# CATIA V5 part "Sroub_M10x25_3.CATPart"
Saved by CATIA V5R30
Part number: Sroub_M10x25_3
Definition: E 1200_10x25
Nomenclature: E 1200_10x25
Source: Unknown
Description: PART--DESC
Bounding box of the stored display mesh (mm): x -163 to -147, y -98 to -82, z -219 to -184
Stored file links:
  E:\Bakalarka\Model\Forma_v7\Sroub_M10x25_3.CATPart
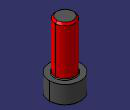
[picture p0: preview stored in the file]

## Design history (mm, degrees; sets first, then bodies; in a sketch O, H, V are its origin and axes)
Body1 "MANIFOLD_SOLID_BREP #4018" (main body)
  Solid1: solid without history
